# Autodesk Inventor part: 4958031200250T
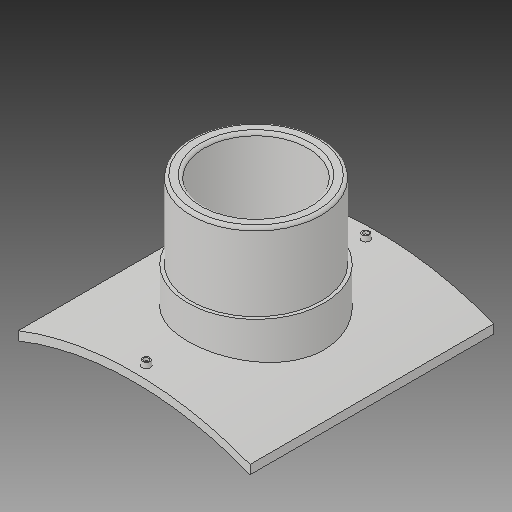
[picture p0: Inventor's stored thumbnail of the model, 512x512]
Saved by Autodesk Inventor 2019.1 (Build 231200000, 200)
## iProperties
Created: 2017-10
Part Number: 4958031200250T
Material: Generic
Description: PLASSON BRANCH SADDLE 1200x250
Document SubType Name: Modeling
Designer: KIM
Mass: 2754.05 g
Surface Area: 3037.44 cm^2
Volume: 2754.05 cm^3
Density: 1 g/cm^3
Appearance: Default
Author: KIM
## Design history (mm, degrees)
derived "495803.ipt"
feature "Solid1::495803.ipt"
tag "TaggingFeature1"
body "Solid1"
other parameters: "d1" = 16, "d2" = 447, "d4" = 0, "d12" = 625.6, "d13" = 14, "d14" = 211.5, "d16" = 5 deg, "d18" = 4, "d19" = 14, "d20" = 0, "d21" = 3, "d22" = 0, "d23" = 829, "d24" = 262.5, "d25" = 16, "d28" = 0, "d29" = 9.6, "d31" = 0, "d32" = 106.5, "d33" = 0, "d34" = 12, "d37" = 149.1, "d38" = 0, "d39" = 6, "B_" = 447, "H_" = 213, "x_" = 16, "D_" = 16
